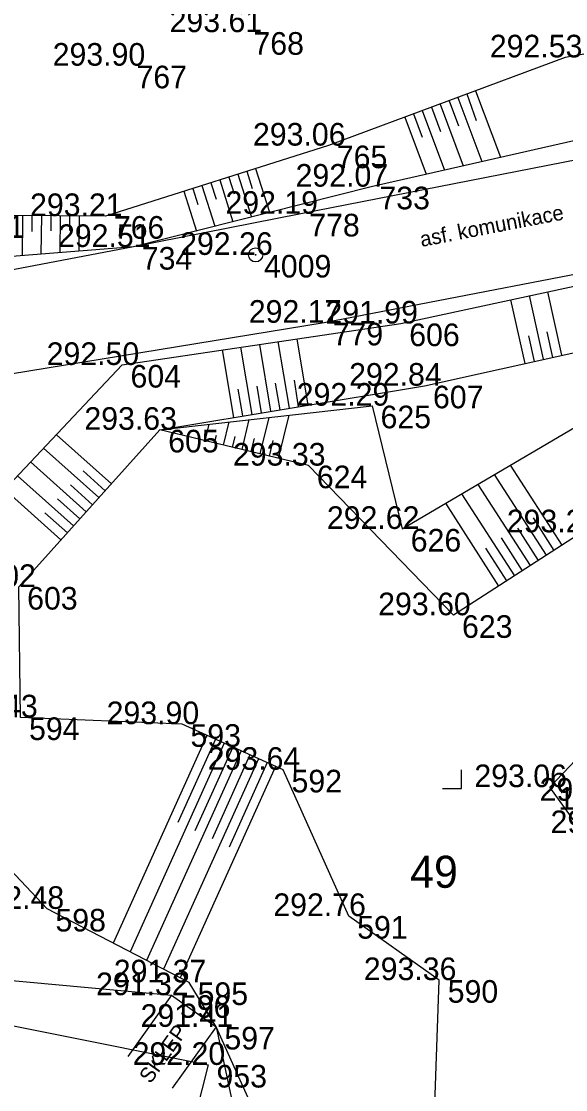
# Model space of a CAD drawing. Extents: x -599970 to -599524, y -1154772 to -1154457.
# Drawn here: x -599732.99 to -599718.56, y -1154635.85 to -1154607.5 of the extents above; entities that cross this region are included whole.
import ezdxf

# ---------------------------------------------------------------- set-up
doc = ezdxf.new("R2010")
doc.units = 0
for name, color, linetype in [('Z-BUDOVY', 7, 'Continuous'), ('Z-KATASTRALNI MAPA', 7, 'Continuous'), ('Z-PEVNE BODY-CISLO', 7, 'Continuous'), ('Z-PEVNE BODY-VYSKA', 7, 'Continuous'), ('Z-PEVNE BODY-ZNACKA', 7, 'Continuous'), ('Z-PODROBNE BODY', 7, 'Continuous'), ('Z-PODROBNE BODY-CISLO', 7, 'Continuous'), ('Z-PODROBNE BODY-VYSKA', 7, 'Continuous'), ('Z-POPISY OBJEKTU A ZPEVNENYCH PLOCH', 7, 'Continuous'), ('Z-SRAFOVANI SVAHU', 7, 'Continuous'), ('Z-TERENNI HRANY PATY', 7, 'Continuous'), ('Z-ZPEVNENE PLOCHY', 7, 'Continuous')]:
    doc.layers.add(name, color=color, linetype=linetype)

msp = doc.modelspace()

# ---------------------------------------------------------------- linework, layer by layer
at = {"layer": 'Z-BUDOVY'}
for p, q in [((-599729.01, -1154633.34), (-599730.17, -1154634.97)), ((-599727.83, -1154634.18), (-599728.99, -1154635.81))]:
    msp.add_line(p, q, dxfattribs=at)
msp.add_lwpolyline([(-599729.01, -1154633.34), (-599727.83, -1154634.18)], dxfattribs=at)
at = {"layer": 'Z-KATASTRALNI MAPA'}
for p, q in [((-599721.32, -1154627.86), (-599721.32, -1154627.36)), ((-599721.821, -1154627.86), (-599721.32, -1154627.86))]:
    msp.add_line(p, q, dxfattribs=at)
at = {"layer": 'Z-PEVNE BODY-ZNACKA'}
for radius in [0.188, 0.188, 0.00896, 0.00896]:
    msp.add_circle((-599726.78, -1154613.7), radius, dxfattribs=at)
at = {"layer": 'Z-PODROBNE BODY'}
for p, q in [((-599727.06, -1154607.79), (-599727.06, -1154607.79)), ((-599718.57, -1154608.46), (-599718.57, -1154608.46)), ((-599730.16, -1154608.68), (-599730.16, -1154608.68)), ((-599724.85, -1154610.8), (-599724.85, -1154610.8)), ((-599723.72, -1154611.89), (-599723.72, -1154611.89)), ((-599730.76, -1154612.67), (-599730.76, -1154612.67)), ((-599725.58, -1154612.61), (-599725.58, -1154612.61)), ((-599730.02, -1154613.49), (-599730.02, -1154613.49)), ((-599724.96, -1154615.5), (-599724.96, -1154615.5)), ((-599722.93, -1154615.52), (-599722.93, -1154615.52)), ((-599730.32, -1154616.62), (-599730.32, -1154616.62)), ((-599722.3, -1154617.17), (-599722.3, -1154617.17)), ((-599723.69, -1154617.7), (-599723.69, -1154617.7)), ((-599729.32, -1154618.34), (-599729.32, -1154618.34)), ((-599725.38, -1154619.29), (-599725.38, -1154619.29)), ((-599722.89, -1154620.97), (-599722.89, -1154620.97)), ((-599721.53, -1154623.26), (-599721.53, -1154623.26)), ((-599728.73, -1154626.15), (-599728.73, -1154626.15)), ((-599726.05, -1154627.36), (-599726.05, -1154627.36)), ((-599718.98, -1154627.82), (-599718.98, -1154627.82)), ((-599732.31, -1154631.05), (-599732.31, -1154631.05)), ((-599724.31, -1154631.24), (-599724.31, -1154631.24)), ((-599721.91, -1154632.94), (-599721.91, -1154632.94)), ((-599728.54, -1154633), (-599728.54, -1154633)), ((-599729.01, -1154633.34), (-599729.01, -1154633.34)), ((-599727.83, -1154634.18), (-599727.83, -1154634.18)), ((-599728.04, -1154635.19), (-599728.04, -1154635.19))]:
    msp.add_line(p, q, dxfattribs=at)
at = {"layer": 'Z-SRAFOVANI SVAHU'}
for points in [[(-599721.18, -1154609.43), (-599720.93, -1154610.13)], [(-599720.95, -1154609.35), (-599720.29, -1154611.11)], [(-599721.89, -1154609.7), (-599721.28, -1154611.34)], [(-599721.65, -1154609.61), (-599721.4, -1154610.28)], [(-599721.42, -1154609.52), (-599720.78, -1154611.22)], [(-599722.59, -1154609.96), (-599722.36, -1154610.58)], [(-599722.36, -1154609.87), (-599721.77, -1154611.45)], [(-599722.12, -1154609.78), (-599721.88, -1154610.43)], [(-599722.82, -1154610.05), (-599722.26, -1154611.56)], [(-599726.78, -1154611.41), (-599726.41, -1154612.57)], [(-599727.73, -1154611.71), (-599727.38, -1154612.82)], [(-599727.49, -1154611.64), (-599727.35, -1154612.08)], [(-599727.25, -1154611.56), (-599726.89, -1154612.7)], [(-599727.01, -1154611.48), (-599726.87, -1154611.94)], [(-599728.68, -1154612.01), (-599728.35, -1154613.07)], [(-599728.44, -1154611.94), (-599728.31, -1154612.36)], [(-599728.21, -1154611.86), (-599727.86, -1154612.94)], [(-599727.97, -1154611.79), (-599727.83, -1154612.22)], [(-599732.96, -1154612.66), (-599732.97, -1154613.72)], [(-599732.71, -1154612.66), (-599732.71, -1154613.08)], [(-599732.46, -1154612.66), (-599732.47, -1154613.68)], [(-599732.21, -1154612.66), (-599732.21, -1154613.06)], [(-599731.96, -1154612.66), (-599731.97, -1154613.64)], [(-599731.71, -1154612.66), (-599731.71, -1154613.05)], [(-599731.46, -1154612.67), (-599731.47, -1154613.6)], [(-599719.15, -1154616.47), (-599719.52, -1154614.78)], [(-599718.66, -1154616.36), (-599719.03, -1154614.68)], [(-599719.63, -1154616.58), (-599720.01, -1154614.89)], [(-599725.39, -1154617.69), (-599725.68, -1154615.93)], [(-599719.39, -1154616.53), (-599719.54, -1154615.85)], [(-599718.9, -1154616.42), (-599719.05, -1154615.74)], [(-599727.36, -1154618.01), (-599727.66, -1154616.22)], [(-599726.87, -1154617.93), (-599727.17, -1154616.15)], [(-599726.38, -1154617.85), (-599726.67, -1154616.08)], [(-599725.88, -1154617.77), (-599726.18, -1154616)], [(-599726.13, -1154617.81), (-599726.25, -1154617.1)], [(-599725.64, -1154617.73), (-599725.75, -1154617.02)], [(-599727.12, -1154617.97), (-599727.24, -1154617.26)], [(-599726.62, -1154617.89), (-599726.74, -1154617.18)], [(-599726.17, -1154619.1), (-599725.89, -1154617.95)], [(-599728.12, -1154618.63), (-599728.01, -1154618.19)], [(-599727.63, -1154618.75), (-599727.48, -1154618.13)], [(-599727.14, -1154618.86), (-599726.95, -1154618.07)], [(-599726.66, -1154618.98), (-599726.42, -1154618.01)], [(-599730.6, -1154619.77), (-599732.06, -1154618.47)], [(-599727.87, -1154618.69), (-599727.82, -1154618.48)], [(-599727.39, -1154618.81), (-599727.32, -1154618.52)], [(-599726.9, -1154618.92), (-599726.81, -1154618.57)], [(-599726.41, -1154619.04), (-599726.31, -1154618.62)], [(-599730.94, -1154620.14), (-599732.4, -1154618.83)], [(-599731.27, -1154620.52), (-599732.75, -1154619.19)], [(-599718.65, -1154621.4), (-599720.02, -1154619.28)], [(-599731.61, -1154620.89), (-599733.09, -1154619.56)], [(-599730.77, -1154619.96), (-599731.35, -1154619.43)], [(-599719.07, -1154621.67), (-599720.45, -1154619.53)], [(-599731.94, -1154621.26), (-599733.43, -1154619.92)], [(-599731.1, -1154620.33), (-599731.69, -1154619.8)], [(-599719.49, -1154621.94), (-599720.88, -1154619.79)], [(-599731.44, -1154620.7), (-599732.03, -1154620.17)], [(-599719.91, -1154622.21), (-599721.31, -1154620.04)], [(-599720.33, -1154622.49), (-599721.74, -1154620.29)], [(-599731.77, -1154621.07), (-599732.37, -1154620.54)], [(-599718.86, -1154621.54), (-599719.41, -1154620.68)], [(-599719.28, -1154621.81), (-599719.83, -1154620.95)], [(-599719.7, -1154622.08), (-599720.26, -1154621.21)], [(-599720.12, -1154622.35), (-599720.68, -1154621.48)], [(-599728.07, -1154626.45), (-599730.56, -1154631.96)], [(-599727.61, -1154626.65), (-599730.11, -1154632.19)], [(-599727.84, -1154626.55), (-599728.84, -1154628.76)], [(-599727.16, -1154626.86), (-599729.67, -1154632.42)], [(-599727.38, -1154626.76), (-599728.39, -1154628.98)], [(-599726.93, -1154626.96), (-599727.93, -1154629.19)], [(-599726.7, -1154627.07), (-599729.22, -1154632.65)], [(-599726.25, -1154627.27), (-599728.78, -1154632.88)], [(-599726.47, -1154627.17), (-599727.48, -1154629.41)]]:
    msp.add_lwpolyline(points, dxfattribs=at)
at = {"layer": 'Z-TERENNI HRANY PATY'}
for points in [[(-599729.05, -1154602.01), (-599721.76, -1154601.98), (-599713.7, -1154601.68), (-599707.23, -1154600.75), (-599702.22, -1154599.95), (-599702.11, -1154604.78), (-599703.83, -1154606.55), (-599707.44, -1154607.94), (-599715.66, -1154610.06), (-599723.72, -1154611.89), (-599730.02, -1154613.49), (-599734.59, -1154613.85), (-599735.4, -1154613.47), (-599737.38, -1154610.51), (-599738.93, -1154607.87), (-599737.97, -1154605.84), (-599735.06, -1154604.09), (-599729.05, -1154602.01)], [(-599706.69, -1154601.61), (-599704.55, -1154601.39), (-599703.42, -1154603.18), (-599703.99, -1154604.61), (-599707.71, -1154606.89), (-599711.67, -1154607.23), (-599718.57, -1154608.46), (-599724.85, -1154610.8), (-599730.76, -1154612.67), (-599734.46, -1154612.65)], [(-599706.85, -1154650.78), (-599713.18, -1154651.03), (-599721.07, -1154652.91), (-599723.76, -1154645.8), (-599725.1, -1154640.23), (-599727.83, -1154634.18), (-599728.54, -1154633), (-599732.31, -1154631.05), (-599735.11, -1154628.08), (-599735.76, -1154623.86), (-599735.73, -1154623.89), (-599734.76, -1154621.33), (-599730.32, -1154616.62), (-599722.93, -1154615.52), (-599713.66, -1154613.52), (-599712.4, -1154614.76), (-599710.05, -1154618.59), (-599710.54, -1154622.05), (-599712.9, -1154623.66), (-599717.25, -1154628.18), (-599716.96, -1154629.04), (-599714.58, -1154631.6), (-599714.4, -1154633.54), (-599711.28, -1154633.06)], [(-599704.68, -1154613.79), (-599704.97, -1154620.78), (-599707.54, -1154629.53), (-599708.11, -1154633.78), (-599709.03, -1154641.46), (-599708.95, -1154648.47), (-599720.11, -1154645.96), (-599722.14, -1154639.54), (-599721.91, -1154632.94), (-599724.31, -1154631.24), (-599726.05, -1154627.36), (-599728.73, -1154626.15), (-599733.01, -1154625.97), (-599733.06, -1154622.51), (-599729.32, -1154618.34), (-599722.3, -1154617.17), (-599714.17, -1154615.37), (-599711.22, -1154619.52), (-599712.8, -1154621.32)], [(-599705.08, -1154613.78), (-599705.62, -1154620.89), (-599708.55, -1154628.74), (-599709.95, -1154633.9), (-599715.55, -1154634.58), (-599716, -1154631.95), (-599718.98, -1154627.82), (-599712.8, -1154621.32)], [(-599729.32, -1154618.34), (-599723.69, -1154617.7), (-599722.89, -1154620.97), (-599716.22, -1154617.04), (-599713.98, -1154617.5), (-599712.6, -1154619.17), (-599711.22, -1154619.52)], [(-599712.8, -1154621.32), (-599715.36, -1154619.38), (-599718.12, -1154621.06), (-599721.53, -1154623.26), (-599725.38, -1154619.29), (-599729.32, -1154618.34)], [(-599737, -1154633.39), (-599735.84, -1154632.71), (-599729.01, -1154633.34)], [(-599737, -1154633.39), (-599728.04, -1154635.19), (-599729.88, -1154642.45), (-599730.13, -1154644.4), (-599731.9, -1154653.11)], [(-599727.83, -1154634.18), (-599726.03, -1154642.59), (-599726.19, -1154645.38), (-599731.9, -1154653.11)]]:
    msp.add_lwpolyline(points, dxfattribs=at)
at = {"layer": 'Z-ZPEVNENE PLOCHY'}
for points in [[(-599671.02, -1154617.03), (-599671.63, -1154613.35), (-599675.05, -1154613.45), (-599680.32, -1154612.41), (-599686.62, -1154610.91), (-599694.45, -1154609.33), (-599700.34, -1154608.57), (-599705.79, -1154608.71), (-599715.78, -1154610.69), (-599725.58, -1154612.61), (-599730.02, -1154613.49), (-599735.64, -1154614.56), (-599743.95, -1154616.26), (-599754.96, -1154619.25), (-599762.63, -1154622.27), (-599761.65, -1154625.43)], [(-599671.02, -1154617.03), (-599674, -1154617.11), (-599674.74, -1154618.09), (-599672.97, -1154619.61), (-599672.99, -1154619.63), (-599673.43, -1154624.97), (-599672.1, -1154632.73), (-599679.37, -1154632.4), (-599679.21, -1154625.35), (-599679.14, -1154619.7), (-599679.61, -1154616.32), (-599687.06, -1154613.66), (-599695, -1154612.23), (-599700.47, -1154611.47), (-599705.51, -1154611.86), (-599715.16, -1154613.61), (-599724.96, -1154615.5), (-599735.23, -1154617.18), (-599743.14, -1154619.2), (-599754.14, -1154621.91)]]:
    msp.add_lwpolyline(points, dxfattribs=at)

# ---------------------------------------------------------------- texts
at = {"layer": 'Z-KATASTRALNI MAPA'}
msp.add_text('49', height=0.85, dxfattribs=at).set_placement((-599722.682, -1154630.49))
at = {"layer": 'Z-PEVNE BODY-CISLO'}
msp.add_text(' 4009', height=0.6, dxfattribs=at).set_placement((-599726.78, -1154614.3))
at = {"layer": 'Z-PEVNE BODY-VYSKA'}
msp.add_text('292.26 ', height=0.6, dxfattribs=at).set_placement((-599728.78, -1154613.7))
at = {"layer": 'Z-PODROBNE BODY-CISLO'}
for s, p in [(' 768', (-599727.06, -1154608.39)), (' 767', (-599730.16, -1154609.28)), (' 765', (-599724.85, -1154611.4)), (' 733', (-599723.72, -1154612.49)), (' 741', (-599734.46, -1154613.25)), (' 766', (-599730.76, -1154613.27)), (' 778', (-599725.58, -1154613.21)), (' 734', (-599730.02, -1154614.09)), (' 779', (-599724.96, -1154616.1)), (' 606', (-599722.93, -1154616.12)), (' 604', (-599730.32, -1154617.22)), (' 607', (-599722.3, -1154617.77)), (' 625', (-599723.69, -1154618.3)), (' 605', (-599729.32, -1154618.94)), (' 624', (-599725.38, -1154619.89)), (' 626', (-599722.89, -1154621.57)), (' 603', (-599733.06, -1154623.11)), (' 623', (-599721.53, -1154623.86)), (' 594', (-599733.01, -1154626.57)), (' 593', (-599728.73, -1154626.75)), (' 592', (-599726.05, -1154627.96)), (' 1001', (-599718.98, -1154628.42)), (' 598', (-599732.31, -1154631.65)), (' 591', (-599724.31, -1154631.84)), (' 595', (-599728.54, -1154633.6)), (' 590', (-599721.91, -1154633.54)), (' 596', (-599729.01, -1154633.94)), (' 597', (-599727.83, -1154634.78)), (' 953', (-599728.04, -1154635.79))]:
    msp.add_text(s, height=0.6, dxfattribs=at).set_placement(p)
at = {"layer": 'Z-PODROBNE BODY-VYSKA'}
for s, p in [('293.61 ', (-599729.06, -1154607.79)), ('292.53 ', (-599720.57, -1154608.46)), ('293.90 ', (-599732.16, -1154608.68)), ('293.06 ', (-599726.85, -1154610.8)), ('292.07 ', (-599725.72, -1154611.89)), ('292.19 ', (-599727.58, -1154612.61)), ('293.21 ', (-599732.76, -1154612.67)), ('292.51 ', (-599732.02, -1154613.49)), ('292.17 ', (-599726.96, -1154615.5)), ('291.99 ', (-599724.93, -1154615.52)), ('292.50 ', (-599732.32, -1154616.62)), ('292.84 ', (-599724.3, -1154617.17)), ('292.29 ', (-599725.69, -1154617.7)), ('293.63 ', (-599731.32, -1154618.34)), ('293.33 ', (-599727.38, -1154619.29)), ('292.62 ', (-599724.89, -1154620.97)), ('293.29 ', (-599720.12, -1154621.06)), ('294.02 ', (-599735.06, -1154622.51)), ('293.60 ', (-599723.53, -1154623.26)), ('294.43 ', (-599735.01, -1154625.97)), ('293.90 ', (-599730.73, -1154626.15)), ('293.64 ', (-599728.05, -1154627.36)), ('293.06 ', (-599720.98, -1154627.82)), ('291.64 ', (-599719.25, -1154628.18)), ('291.67 ', (-599718.96, -1154629.04)), ('292.48 ', (-599734.31, -1154631.05)), ('292.76 ', (-599726.31, -1154631.24)), ('291.37 ', (-599730.54, -1154633)), ('293.36 ', (-599723.91, -1154632.94)), ('291.32 ', (-599731.01, -1154633.34)), ('291.41 ', (-599729.83, -1154634.18)), ('292.20 ', (-599730.04, -1154635.19))]:
    msp.add_text(s, height=0.6, dxfattribs=at).set_placement(p)
at = {"layer": 'Z-POPISY OBJEKTU A ZPEVNENYCH PLOCH'}
for s, rotation, p in [('asf. komunikace', 10.9159, (-599722.38, -1154613.49)), ('SKLEP', 54.5622, (-599729.57, -1154635.71))]:
    msp.add_text(s, height=0.4, rotation=rotation, dxfattribs=at).set_placement(p)

doc.saveas('drawing.dxf')
